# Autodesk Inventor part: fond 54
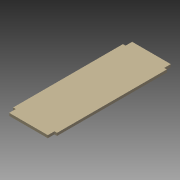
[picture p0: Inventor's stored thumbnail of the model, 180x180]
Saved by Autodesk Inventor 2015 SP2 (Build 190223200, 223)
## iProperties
Created: 2015-08
Part Number: fond 54
Material: Générique
Document SubType Name: Modeling
Designer: Dominique
Density: 1 g/cm^3
Appearance: Beige
Author: Dominique
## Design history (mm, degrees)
sketch "Esquisse1"
  geometry: L1 (2.64, -0.9)-(46.64, -0.9); L2 (49.64, 6.6)-(49.64, 131.6); L3 (46.64, 139.1)-(2.64, 139.1); L4 (-0.36, 131.6)-(-0.36, 6.6); L5 (2.64, 139.1)-(2.64, 131.6); L6 (2.64, 131.6)-(-0.36, 131.6); L7 (46.64, 139.1)-(46.64, 131.6); L8 (46.64, 131.6)-(49.64, 131.6); L9 (2.64, -0.9)-(2.64, 6.6); L10 (2.64, 6.6)-(-0.36, 6.6); L11 (46.64, -0.9)-(46.64, 6.6); L12 (46.64, 6.6)-(49.64, 6.6); 1 further point
  constraints: 24 end point, 3 point on line, 2 parallel, 1 horizontal, 1 perpendicular
  dimensions: "d9" = 44 distance between parallel lines of L7 L5; "d10" = 140 distance between parallel lines of L1 L3; "d11" = 7.5 distance between parallel lines of L3 L6; "d12" = 7.5 distance between parallel lines of L3 L8; "d13" = 7.5 distance between parallel lines of L1 L10; "d14" = 3 distance between parallel lines of L5 L4; "d15" = 3 distance between parallel lines of L2 L7; "d16" = 3 distance between parallel lines of L2 L11 (derived); "d17" = 3 distance between parallel lines of L9 L4 (derived)
extrude "Extrusion1" new body sketch "Esquisse1" distance "d7" = 3; taper "d8" = 0 deg
node "Solide1"
